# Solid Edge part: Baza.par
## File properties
Author: Ionut
Template: Normal.par
Last saved by: Ionut
Revision: 2
Application: Solid Edge
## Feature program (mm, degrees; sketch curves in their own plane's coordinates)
sketch for "unnamed Protrusion 1" #1 plane through (0, 0, 0) normal (0, 0, 1) x-axis (1, 0, 0)
  line (-11.8143, 8) -> (-31.8143, 8)
  line (-31.8143, 8) -> (-31.8143, -8)
  line (-11.8143, -8) -> (-31.8143, -8)
  line (-11.8143, -8) -> (-11.8143, 8)
sketch for "unnamed Protrusion 1" #2 plane through (0, 0, 0) normal (0, 0, 1) x-axis (1, 0, 0)
  line (5.3707, -14.3262) -> (15.3857, 3.0203)
  line (15.3857, 3.0203) -> (32.7062, -6.9797)
  line (22.6912, -24.3262) -> (32.7062, -6.9797)
  line (5.3707, -14.3262) -> (22.6912, -24.3262)
extrude "unnamed Protrusion 1" add finite 20 along +normal
sketch for "unnamed Hole 1" plane through (27.6987, -15.653, 10) normal (0.866025, -0.5, 0) x-axis (0.5, 0.866025, 0)
  hole centre (0, 1) bore radius 4
hole "unnamed Hole 1" through
sketch for "unnamed Hole 2" plane through (-31.8143, 0, 10) normal (-1, 0, 0) x-axis (0, -1, 0)
  hole centre (0, 1) bore radius 4
hole "unnamed Hole 2" through
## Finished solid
Body 1: solid body, 14 faces, 28 edges, 16 vertices, 2 separate solids.
  Faces by surface: plane 12, cylinder 2
  Edges by curve: line 24, circle 4
Bounding box of the edges (mm): 64.520 x 32.326 x 20.000, from (-31.8143, -24.3262, 0) to (32.7062, 8, 20).
Cylindrical faces by radius (mm): R4 x2
Planar faces by outward normal: +x 1, +y 1, +z 2, -x 1, -y 1, -z 2, oblique 4
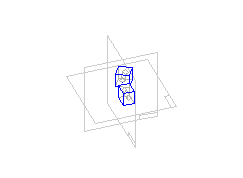
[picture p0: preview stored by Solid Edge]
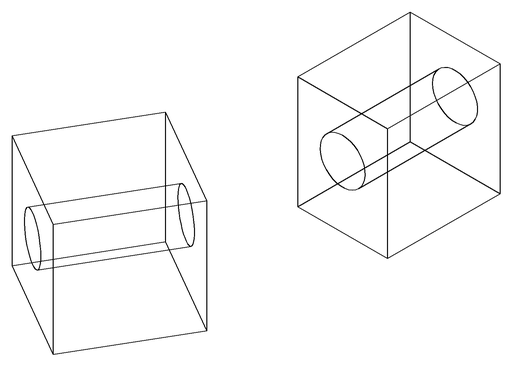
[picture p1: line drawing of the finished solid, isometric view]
